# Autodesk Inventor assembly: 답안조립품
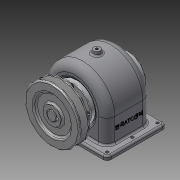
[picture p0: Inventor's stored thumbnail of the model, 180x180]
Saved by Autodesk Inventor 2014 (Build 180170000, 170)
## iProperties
Created: 2015-09
Part Number: 답안조립품
Document SubType Name: Assembly
Designer: Administrator
Author: Administrator
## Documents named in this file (14)
- C:\Users\Administrator\Desktop\450907V1047\답안조립품.iam
- C:\Users\Administrator\Desktop\450907V1047\1-본체.ipt
- C:\Users\Administrator\Desktop\450907V1047\V-벨트풀리.ipt
- C:\Users\Administrator\Desktop\450907V1047\뒤커버.ipt
- C:\Users\Administrator\Desktop\450907V1047\멈춤나사 - M4x10.ipt
- C:\Users\Administrator\Desktop\450907V1047\베어링 6203.ipt
- C:\Users\Administrator\Desktop\450907V1047\볼트 M3 x 8.ipt
- C:\Users\Administrator\Desktop\450907V1047\볼트 M3 x 10.ipt
- C:\Users\Administrator\Desktop\450907V1047\스퍼기어.ipt
- C:\Users\Administrator\Desktop\450907V1047\앞커버.ipt
- C:\Users\Administrator\Desktop\450907V1047\오일 실 17 32 8.ipt
- C:\Users\Administrator\Desktop\450907V1047\축.ipt
- C:\Users\Administrator\Desktop\450907V1047\키 - 5 x 5 x 18.ipt
- C:\Users\Administrator\Desktop\450907V1047\키 - 6 x 6 x 22.ipt
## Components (7 placed, 4 different names)
1. 1-본체:1 — 플러쉬:1, 플러쉬:2
2. V-벨트풀리:1
3. ISO 4762 M3 x 10:1
4. ISO 4762 M3 x 8:1
5. ISO 4762 M3 x 8:2
6. ISO 4762 M3 x 8:3
7. ISO 4762 M3 x 8:4
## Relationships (2: Flush 2)
- 플러쉬:1 [Flush]: 1-본체:1
- 플러쉬:2 [Flush]: 1-본체:1
